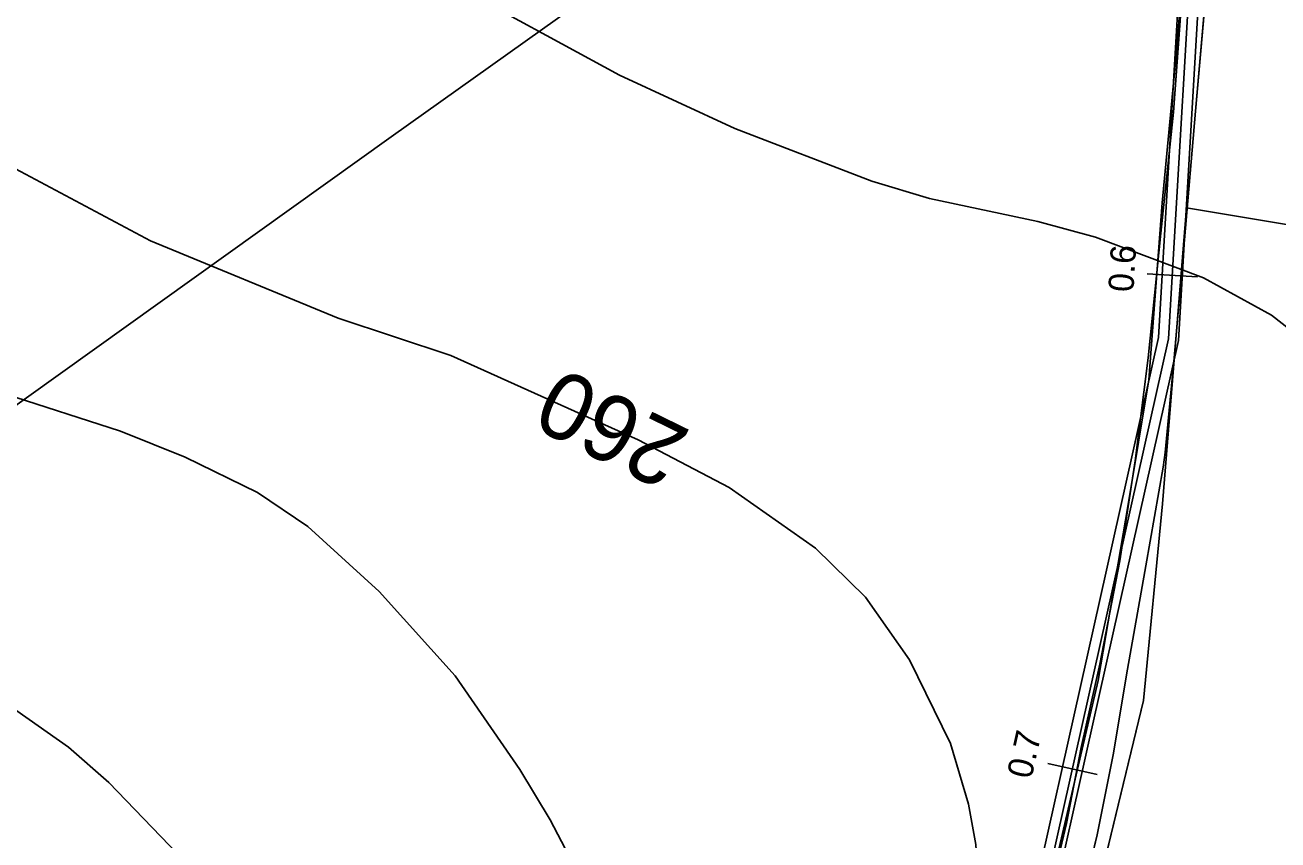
# Model space of a CAD drawing. Extents: x -662620 to -656370, y -1067090 to -1062990.
# Drawn here: x -658687 to -658438.7, y -1065815.5 to -1065654 of the extents above; entities that cross this region are included whole.
import ezdxf

# ---------------------------------------------------------------- set-up
doc = ezdxf.new("R2010")
doc.units = 0
for name, color, linetype in [('Agrotechnicka_opatreni_hrazkovani_a_dulkovani__mulcovani', 7, 'Continuous'), ('Default', 7, 'Continuous'), ('ELEK__VEDENÍ_VN_-_NADZEMNÍ', 7, 'Continuous'), ('ORNÁ_PŮDA_-_STÁVAJÍCÍ', 7, 'Continuous'), ('OSTATNÍ_PLOCHA_-_STÁVAJÍCÍ', 7, 'Continuous'), ('OVOCNÝ_SAD_-_NAVRŽENÝ', 7, 'Continuous'), ('POLNÍ_CESTA_STÁVAJÍCÍ_-_KRAJ', 7, 'Continuous'), ('POLNÍ_CESTA_STÁVAJÍCÍ_-_OSA', 7, 'Continuous'), ('VRSTEVNICE_ZDŮRAZNĚNÁ', 7, 'Continuous'), ('VRSTEVNICE_ZDŮRAZNĚNÁ_-_POPIS', 7, 'Continuous'), ('VRSTEVNICE_ZÁKLADNÍ', 7, 'Continuous')]:
    doc.layers.add(name, color=color, linetype=linetype)

msp = doc.modelspace()

# ---------------------------------------------------------------- linework, layer by layer
at = {"layer": 'Agrotechnicka_opatreni_hrazkovani_a_dulkovani__mulcovani'}
msp.add_lwpolyline([(-658454.8, -1065610.1), (-658459, -1065660.6), (-658461.7, -1065689.2), (-658464.3, -1065724.3), (-658468.4, -1065749), (-658474.4, -1065783.9), (-658495.1, -1065872.9), (-658497.1, -1065881.9), (-658511.2, -1065934.8), (-658524.2, -1065990.5), (-658533.1, -1066025.5), (-658537.5, -1066046.3), (-658542, -1066058.5), (-658543.7, -1066062.3), (-658550.4, -1066062.7), (-658558.89, -1066061.79), (-658593.12, -1066055.27), (-658662.77, -1066041.21), (-658696.34, -1066031.17)], dxfattribs=at)
at = {"layer": 'ELEK__VEDENÍ_VN_-_NADZEMNÍ'}
msp.add_lwpolyline([(-659283.51, -1066152.49), (-659200.82, -1066093.95), (-659094.6, -1066018.18), (-659022.28, -1065966.69), (-658937.63, -1065906.48), (-658856.53, -1065848.35), (-658776.07, -1065791.16), (-658693.11, -1065732.39), (-658614.47, -1065676.12), (-658531.84, -1065617.27), (-658444.6, -1065555.07), (-658431.73, -1065546.01)], dxfattribs=at)
at = {"layer": 'ORNÁ_PŮDA_-_STÁVAJÍCÍ'}
for p, q in [((-658457.6, -1065645.85), (-658459.45, -1065671.27)), ((-658455.06, -1065671.07), (-658453, -1065647.06)), ((-658459.45, -1065671.27), (-658461.93, -1065695.25)), ((-658457.26, -1065696.56), (-658455.06, -1065671.07)), ((-658461.93, -1065695.25), (-658464.45, -1065719.98)), ((-658459.34, -1065719.98), (-658457.26, -1065696.56)), ((-658464.45, -1065719.98), (-658467.03, -1065740.36)), ((-658461.08, -1065738.75), (-658459.34, -1065719.98)), ((-658461.51, -1065741.65), (-658461.08, -1065738.75)), ((-658467.03, -1065740.36), (-658470.05, -1065760.17)), ((-658464.91, -1065761.21), (-658461.51, -1065741.65)), ((-658470.05, -1065760.17), (-658474.01, -1065780.69)), ((-658468.74, -1065782.81), (-658464.91, -1065761.21)), ((-658474.01, -1065780.69), (-658477.73, -1065797.18)), ((-658471.36, -1065798.31), (-658468.74, -1065782.81)), ((-658477.73, -1065797.18), (-658480.67, -1065812.29)), ((-658474.55, -1065814.53), (-658471.36, -1065798.31)), ((-658480.67, -1065812.29), (-658485.47, -1065832.33)), ((-658478.38, -1065830.32), (-658474.55, -1065814.53))]:
    msp.add_line(p, q, dxfattribs=at)
for points in [[(-658457.6, -1065645.85), (-658459.45, -1065671.27), (-658461.93, -1065695.25), (-658464.45, -1065719.98), (-658467.03, -1065740.36), (-658470.05, -1065760.17), (-658474.01, -1065780.69), (-658477.73, -1065797.18), (-658480.67, -1065812.29), (-658485.47, -1065832.33)], [(-658478.38, -1065830.32), (-658474.55, -1065814.53), (-658471.36, -1065798.31), (-658468.74, -1065782.81), (-658464.91, -1065761.21), (-658461.51, -1065741.65), (-658461.08, -1065738.75), (-658459.34, -1065719.98), (-658457.26, -1065696.56), (-658455.06, -1065671.07), (-658453, -1065647.06)]]:
    msp.add_lwpolyline(points, dxfattribs=at)
at = {"layer": 'OSTATNÍ_PLOCHA_-_STÁVAJÍCÍ'}
for p, q in [((-658459.45, -1065671.27), (-658457.6, -1065645.85)), ((-658459.45, -1065671.27), (-658457.6, -1065645.85)), ((-658453, -1065647.06), (-658455.06, -1065671.07)), ((-658453, -1065647.06), (-658455.06, -1065671.07)), ((-658461.93, -1065695.25), (-658459.45, -1065671.27)), ((-658461.93, -1065695.25), (-658459.45, -1065671.27)), ((-658455.06, -1065671.07), (-658457.26, -1065696.56)), ((-658455.06, -1065671.07), (-658457.26, -1065696.56)), ((-658464.45, -1065719.98), (-658461.93, -1065695.25)), ((-658464.45, -1065719.98), (-658461.93, -1065695.25)), ((-658457.26, -1065696.56), (-658459.34, -1065719.98)), ((-658457.26, -1065696.56), (-658459.34, -1065719.98)), ((-658467.03, -1065740.36), (-658464.45, -1065719.98)), ((-658467.03, -1065740.36), (-658464.45, -1065719.98)), ((-658459.34, -1065719.98), (-658461.08, -1065738.75)), ((-658459.34, -1065719.98), (-658461.08, -1065738.75)), ((-658461.08, -1065738.75), (-658461.51, -1065741.65)), ((-658461.08, -1065738.75), (-658461.51, -1065741.65)), ((-658470.05, -1065760.17), (-658467.03, -1065740.36)), ((-658470.05, -1065760.17), (-658467.03, -1065740.36)), ((-658461.51, -1065741.65), (-658464.91, -1065761.21)), ((-658461.51, -1065741.65), (-658464.91, -1065761.21)), ((-658474.01, -1065780.69), (-658470.05, -1065760.17)), ((-658474.01, -1065780.69), (-658470.05, -1065760.17)), ((-658464.91, -1065761.21), (-658468.74, -1065782.81)), ((-658464.91, -1065761.21), (-658468.74, -1065782.81)), ((-658477.73, -1065797.18), (-658474.01, -1065780.69)), ((-658477.73, -1065797.18), (-658474.01, -1065780.69)), ((-658468.74, -1065782.81), (-658471.36, -1065798.31)), ((-658468.74, -1065782.81), (-658471.36, -1065798.31)), ((-658480.67, -1065812.29), (-658477.73, -1065797.18)), ((-658480.67, -1065812.29), (-658477.73, -1065797.18)), ((-658471.36, -1065798.31), (-658474.55, -1065814.53)), ((-658471.36, -1065798.31), (-658474.55, -1065814.53)), ((-658485.47, -1065832.33), (-658480.67, -1065812.29)), ((-658485.47, -1065832.33), (-658480.67, -1065812.29)), ((-658474.55, -1065814.53), (-658478.38, -1065830.32)), ((-658474.55, -1065814.53), (-658478.38, -1065830.32))]:
    msp.add_line(p, q, dxfattribs=at)
for points in [[(-658485.47, -1065832.33), (-658480.67, -1065812.29), (-658477.73, -1065797.18), (-658474.01, -1065780.69), (-658470.05, -1065760.17), (-658467.03, -1065740.36), (-658464.45, -1065719.98), (-658461.93, -1065695.25), (-658459.45, -1065671.27), (-658457.6, -1065645.85)], [(-658485.47, -1065832.33), (-658480.67, -1065812.29), (-658477.73, -1065797.18), (-658474.01, -1065780.69), (-658470.05, -1065760.17), (-658467.03, -1065740.36), (-658464.45, -1065719.98), (-658461.93, -1065695.25), (-658459.45, -1065671.27), (-658457.6, -1065645.85)], [(-658453, -1065647.06), (-658455.06, -1065671.07), (-658457.26, -1065696.56), (-658459.34, -1065719.98), (-658461.08, -1065738.75), (-658461.51, -1065741.65), (-658464.91, -1065761.21), (-658468.74, -1065782.81), (-658471.36, -1065798.31), (-658474.55, -1065814.53), (-658478.38, -1065830.32)], [(-658453, -1065647.06), (-658455.06, -1065671.07), (-658457.26, -1065696.56), (-658459.34, -1065719.98), (-658461.08, -1065738.75), (-658461.51, -1065741.65), (-658464.91, -1065761.21), (-658468.74, -1065782.81), (-658471.36, -1065798.31), (-658474.55, -1065814.53), (-658478.38, -1065830.32)]]:
    msp.add_lwpolyline(points, dxfattribs=at)
at = {"layer": 'OVOCNÝ_SAD_-_NAVRŽENÝ'}
for p, q in [((-658461.6, -1065748.9), (-658456.9, -1065690.2)), ((-658456.9, -1065690.2), (-658313.2, -1065714.2)), ((-658465.4, -1065787.9), (-658461.6, -1065748.9)), ((-658491.5, -1065895.8), (-658465.4, -1065787.9))]:
    msp.add_line(p, q, dxfattribs=at)
msp.add_lwpolyline([(-658313.74, -1065716.61), (-658350.95, -1065883.3), (-658397.29, -1066090.9), (-658398.3, -1066095.4), (-658422.68, -1066089.69), (-658422.63, -1066089.51), (-658443.73, -1066084.72), (-658443.76, -1066084.83), (-658491, -1066076), (-658510.2, -1066072.3), (-658523.4, -1066069.5), (-658528.1, -1066066.8), (-658530.1, -1066062.8), (-658502.8, -1065945.7), (-658491.5, -1065895.8), (-658465.4, -1065787.9), (-658461.6, -1065748.9), (-658456.9, -1065690.2), (-658313.2, -1065714.2)], close=True, dxfattribs=at)
at = {"layer": 'POLNÍ_CESTA_STÁVAJÍCÍ_-_KRAJ'}
for points in [[(-658485.55, -1065108.25), (-658454.64, -1065229.3), (-658443.22, -1065313.45), (-658441.54, -1065428.79), (-658458.43, -1065716.49), (-658538.19, -1066073.35)], [(-658489.42, -1065109.24), (-658458.57, -1065230.06), (-658447.22, -1065313.74), (-658445.54, -1065428.7), (-658462.4, -1065715.93), (-658542.09, -1066072.48)]]:
    msp.add_lwpolyline(points, dxfattribs=at)
at = {"layer": 'POLNÍ_CESTA_STÁVAJÍCÍ_-_OSA'}
for points in [[(-658487.49, -1065108.74), (-658456.6, -1065229.68), (-658445.22, -1065313.6), (-658443.54, -1065428.75), (-658460.42, -1065716.21), (-658540.14, -1066072.91)], [(-658454.69, -1065703.9), (-658464.67, -1065703.32)], [(-658474.6, -1065802.57), (-658484.35, -1065800.39)]]:
    msp.add_lwpolyline(points, dxfattribs=at)
at = {"layer": 'VRSTEVNICE_ZDŮRAZNĚNÁ'}
msp.add_lwpolyline([(-658751.34, -1065652.76), (-658725.33, -1065664.05), (-658691.88, -1065680.92), (-658662.15, -1065696.79), (-658624.99, -1065712.08), (-658602.69, -1065719.51), (-658565.53, -1065736.24), (-658547.52, -1065745.67), (-658530.36, -1065757.68), (-658520.5, -1065767.39), (-658511.78, -1065779.83), (-658503.63, -1065796.41), (-658500.06, -1065808.42), (-658498.63, -1065816.42), (-658495.49, -1065868.45), (-658495.49, -1065884.17), (-658497.2, -1065921.91), (-658496.44, -1065943.99)], dxfattribs=at)
at = {"layer": 'VRSTEVNICE_ZÁKLADNÍ'}
for points in [[(-658591.52, -1065932.36), (-658599.4, -1065914.47), (-658608.83, -1065891.6), (-658615.27, -1065878.74), (-658628.99, -1065855.87), (-658641.99, -1065836.86), (-658656.72, -1065818.42), (-658670.44, -1065804.13), (-658678.44, -1065797.12), (-658694.74, -1065785.69), (-658724.47, -1065768.82), (-658743.48, -1065756.67), (-658750.34, -1065751.1), (-658777.92, -1065725.37), (-658818.8, -1065690.21), (-658858.4, -1065659.19), (-658873.26, -1065648.62), (-658886.84, -1065640.18), (-658905.13, -1065632.18), (-658916.57, -1065629.04), (-658929.15, -1065626.61), (-658940.58, -1065625.75), (-658970.45, -1065626.03)], [(-658591.52, -1065932.36), (-658599.4, -1065914.47), (-658608.83, -1065891.6), (-658615.27, -1065878.74), (-658628.99, -1065855.87), (-658641.99, -1065836.86), (-658656.72, -1065818.42), (-658670.44, -1065804.13), (-658678.44, -1065797.12), (-658694.74, -1065785.69), (-658724.47, -1065768.82), (-658743.48, -1065756.67), (-658750.34, -1065751.1), (-658777.92, -1065725.37), (-658818.8, -1065690.21), (-658858.4, -1065659.19), (-658873.26, -1065648.62), (-658886.84, -1065640.18), (-658905.13, -1065632.18), (-658916.57, -1065629.04), (-658929.15, -1065626.61), (-658940.58, -1065625.75), (-658970.45, -1065626.03)], [(-658830.52, -1065643.33), (-658803.22, -1065663.63), (-658779.07, -1065680.35), (-658733.9, -1065706.51), (-658705.31, -1065721.51), (-658691.02, -1065727.09), (-658668.15, -1065734.52), (-658655.29, -1065739.67), (-658640.99, -1065746.67), (-658630.99, -1065753.39), (-658616.84, -1065766.25), (-658601.83, -1065782.97), (-658588.97, -1065801.56), (-658582.96, -1065811.56), (-658569.39, -1065837.57), (-658557.09, -1065869.59), (-658552.23, -1065885.6), (-658549.66, -1065901.61), (-658548.09, -1065921.62), (-658546.78, -1065937.83)], [(-658830.52, -1065643.33), (-658803.22, -1065663.63), (-658779.07, -1065680.35), (-658733.9, -1065706.51), (-658705.31, -1065721.51), (-658691.02, -1065727.09), (-658668.15, -1065734.52), (-658655.29, -1065739.67), (-658640.99, -1065746.67), (-658630.99, -1065753.39), (-658616.84, -1065766.25), (-658601.83, -1065782.97), (-658588.97, -1065801.56), (-658582.96, -1065811.56), (-658569.39, -1065837.57), (-658557.09, -1065869.59), (-658552.23, -1065885.6), (-658549.66, -1065901.61), (-658548.09, -1065921.62), (-658546.78, -1065937.83)], [(-658434.88, -1065715.51), (-658440.03, -1065711.51), (-658453.47, -1065704.08), (-658474.91, -1065696.07), (-658486.34, -1065692.93), (-658507.78, -1065688.35), (-658519.22, -1065684.92), (-658546.37, -1065674.49), (-658569.24, -1065663.91), (-658592.11, -1065651.48)], [(-658434.88, -1065715.51), (-658440.03, -1065711.51), (-658453.47, -1065704.08), (-658474.91, -1065696.07), (-658486.34, -1065692.93), (-658507.78, -1065688.35), (-658519.22, -1065684.92), (-658546.37, -1065674.49), (-658569.24, -1065663.91), (-658592.11, -1065651.48)]]:
    msp.add_lwpolyline(points, dxfattribs=at)

# ---------------------------------------------------------------- texts
at = {"layer": 'Default'}
for s, rotation, p in [('0.6', 86.6403, (-658467.39, -1065707.01)), ('0.7', 77.4019, (-658487.63, -1065803.6))]:
    msp.add_text(s, height=5, rotation=rotation, dxfattribs=at).set_placement(p)
at = {"layer": 'VRSTEVNICE_ZDŮRAZNĚNÁ_-_POPIS'}
msp.add_text('260', height=13.2, rotation=153.9, dxfattribs=at).set_placement((-658554.72, -1065734.57))

doc.saveas('drawing.dxf')
